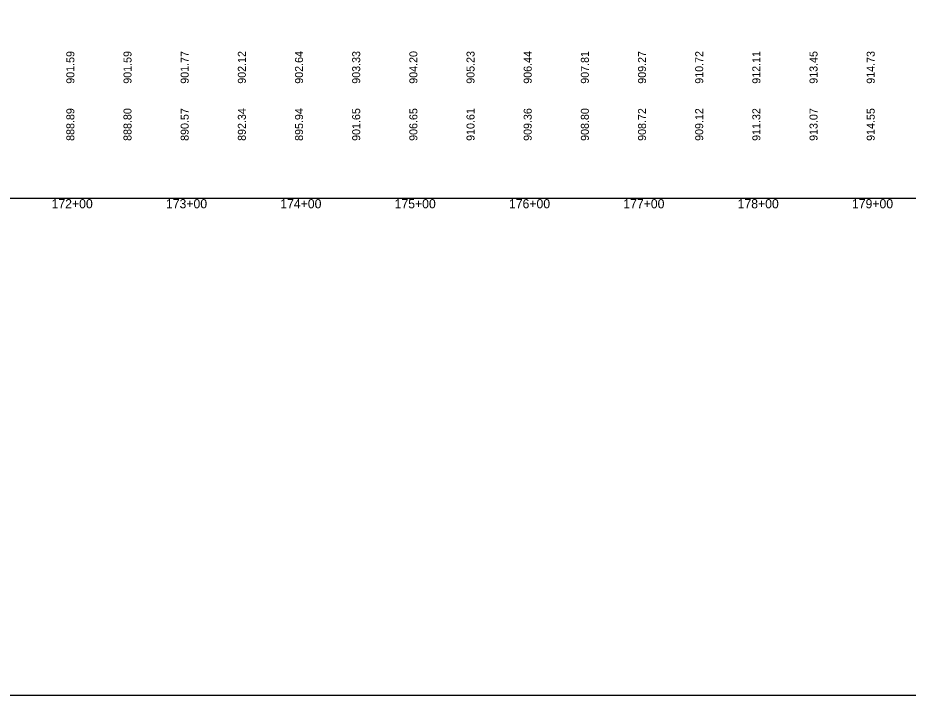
# Model space of a CAD drawing. Extents: x 1475774 to 1484571, y 1098511 to 1113011.
# Drawn here: x 1479921 to 1480699, y 1103076 to 1103669 of the extents above; entities that cross this region are included whole.
import ezdxf

# ---------------------------------------------------------------- set-up
doc = ezdxf.new("R2010")
doc.units = 0
for name, color, linetype in [('RD_DDB_StaTX', 7, 'Continuous'), ('RD_DDB_StripGrade', 7, 'Continuous'), ('RD_GPK_Profile_Cell', 7, 'Continuous'), ('RD_Sketch5', 7, 'Continuous')]:
    doc.layers.add(name, color=color, linetype=linetype)

msp = doc.modelspace()

# ---------------------------------------------------------------- linework, layer by layer
at = {"layer": 'RD_GPK_Profile_Cell'}
msp.add_line((1477570.98, 1103511.25), (1484570.98, 1103511.25), dxfattribs=at)
at = {"layer": 'RD_Sketch5'}
msp.add_lwpolyline([(1477722.71, 1103076.18), (1481322.71, 1103076.18), (1481322.71, 1105276.18), (1477722.71, 1105276.18)], close=True, dxfattribs=at)

# ---------------------------------------------------------------- texts
at = {"layer": 'RD_DDB_StaTX'}
for s, p in [('172+00', (1479950.09, 1103502.25)), ('173+00', (1480050.09, 1103502.25)), ('174+00', (1480150.09, 1103502.25)), ('175+00', (1480250.09, 1103502.25)), ('176+00', (1480350.09, 1103502.25)), ('177+00', (1480450.09, 1103502.25)), ('178+00', (1480550.09, 1103502.25)), ('179+00', (1480650.09, 1103502.25))]:
    msp.add_text(s, height=8, dxfattribs=at).set_placement(p)
at = {"layer": 'RD_DDB_StripGrade'}
for s, p in [('901.59', (1479969.98, 1103611.25)), ('901.59', (1480019.98, 1103611.25)), ('901.77', (1480069.98, 1103611.25)), ('902.12', (1480119.98, 1103611.25)), ('902.64', (1480169.98, 1103611.25)), ('903.33', (1480219.98, 1103611.25)), ('904.20', (1480269.98, 1103611.25)), ('905.23', (1480319.98, 1103611.25)), ('906.44', (1480369.98, 1103611.25)), ('907.81', (1480419.98, 1103611.25)), ('909.27', (1480469.98, 1103611.25)), ('910.72', (1480519.98, 1103611.25)), ('912.11', (1480569.98, 1103611.25)), ('913.45', (1480619.98, 1103611.25)), ('914.73', (1480669.98, 1103611.25)), ('888.89', (1479969.98, 1103561.25)), ('888.80', (1480019.98, 1103561.25)), ('890.57', (1480069.98, 1103561.25)), ('892.34', (1480119.98, 1103561.25)), ('895.94', (1480169.98, 1103561.25)), ('901.65', (1480219.98, 1103561.25)), ('906.65', (1480269.98, 1103561.25)), ('910.61', (1480319.98, 1103561.25)), ('909.36', (1480369.98, 1103561.25)), ('908.80', (1480419.98, 1103561.25)), ('908.72', (1480469.98, 1103561.25)), ('909.12', (1480519.98, 1103561.25)), ('911.32', (1480569.98, 1103561.25)), ('913.07', (1480619.98, 1103561.25)), ('914.55', (1480669.98, 1103561.25))]:
    msp.add_text(s, height=7, rotation=90, dxfattribs=at).set_placement(p)

doc.saveas('drawing.dxf')
